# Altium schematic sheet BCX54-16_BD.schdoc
size 127 x 101 mm
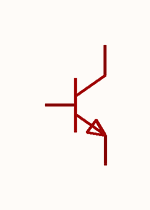
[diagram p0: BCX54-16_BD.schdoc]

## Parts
Q?  bcx54-16(range:100-250)  [SOT-89-3_L4.5-W2.5-P1.50-LS4.2-BR]  (value not drawn)

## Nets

Not connected (* = marked no-connect by the designer): Q? 1(B) 2(C) 3(E)

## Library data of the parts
Q? = bcx54-16(range:100-250): 晶体管类型:NPN;集电极电流(Ic):1A;集射极击穿电压(Vceo):45V;耗散功率(Pd):500mW;直流电流增益(hFE):100;; Manufacturer: CJ(江苏长电/长晶); Symbol: BCX54-16:BD; AddInBom: yes; ModelId: 6db690b7897d4d18a30d90c1b89525ee; ModelName: SOT-89-3_L4.3-W2.5-H1.6-LS4.1-P1.50; ModelTransform: 161.417,169.291,0,180,0,0,-18.661,0,0; type: NPN; Current - Collector(Ic): 1A; Collector - Emitter Voltage VCEO: 45V; Pd - Power Dissipation: 500mW; DC Current Gain: 100; Transition frequency(fT): 130MHz; Current - Collector Cutoff: 100nA; Vce Saturation(VCE(sat)): 500mV; Emitter-Base Voltage(Vebo): 5V; Number: 1个NPN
